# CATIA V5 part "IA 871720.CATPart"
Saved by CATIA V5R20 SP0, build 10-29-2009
Part number: IA 871720
Revision: ANY
Definition: UNKNOWN
Nomenclature: IA 871720
Source: Unknown
Bounding box of the stored display mesh (mm): x -4.35 to 4.35, y -17 to 0, z -4.35 to 4.35
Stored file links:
  C:\Users\Utente\Desktop\IO LAVORO\3D X SITO CF\CUMSA\3D files FA\FA 168712-20\IA 871720.CATPart

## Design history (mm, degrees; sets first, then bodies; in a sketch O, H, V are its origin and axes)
Body1 "Cortar-Extruir3" (main body)
  Solid1: solid without history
